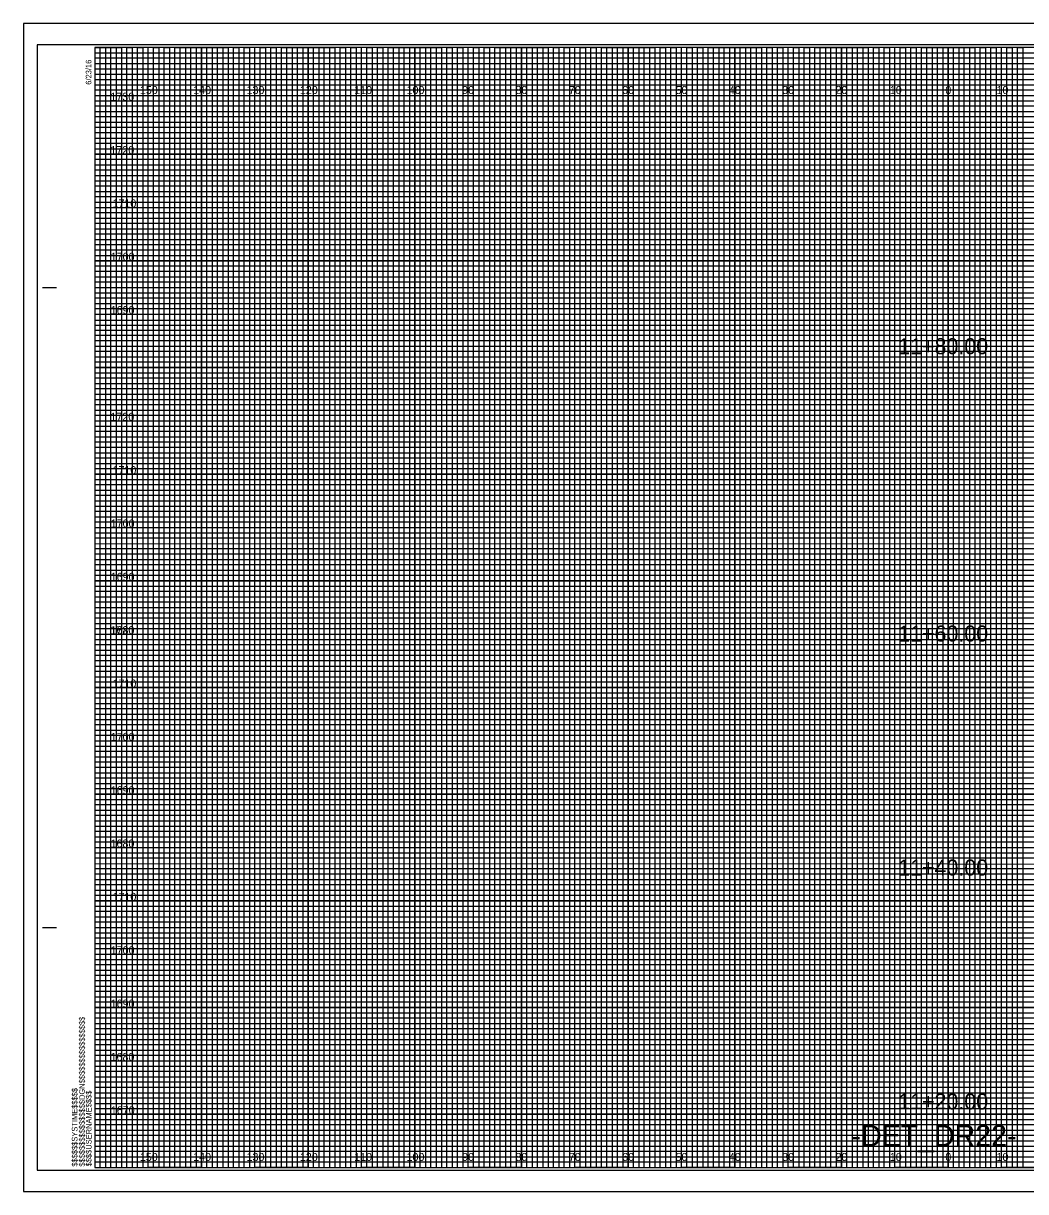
# Model space of a CAD drawing. Extents: x -13 to 323, y -5 to 1314.
# Drawn here: x -13.4 to 174.5, y 215.5 to 434.5 of the extents above; entities that cross this region are included whole.
import ezdxf

# ---------------------------------------------------------------- set-up
doc = ezdxf.new("R2010")
doc.units = 0
for name, color, linetype in [('Prop Horizontal Alignment', 7, 'Continuous'), ('Prop XS Alignment Label', 7, 'Continuous'), ('Raster_Level_0', 7, 'Continuous'), ('Scratch_Level_3', 7, 'Continuous'), ('Sheet Cross Section CELL', 7, 'Continuous'), ('Sheet Cross Section Grid Major CELL', 7, 'Continuous'), ('Sheet Cross Section Grid Middle CELL', 7, 'Continuous'), ('Sheet Cross Section Grid Minor 1 CELL', 7, 'Continuous'), ('Sheet Cross Section Grid Minor 2 CELL', 7, 'Continuous'), ('Sheet Cutting Line CELL', 7, 'Continuous'), ('Sheet DOT Grid CELL', 7, 'Continuous'), ('Sheet Plot Border Inside CELL', 7, 'Continuous'), ('Sheet Plot Border Outside CELL', 7, 'Continuous')]:
    doc.layers.add(name, color=color, linetype=linetype)

msp = doc.modelspace()

# ---------------------------------------------------------------- linework, layer by layer
at = {"layer": 'Sheet Cross Section CELL'}
for p, q in [((-9.8, 385), (-7.3, 385)), ((-9.7, 385), (-7.2, 385)), ((-9.8, 265), (-7.3, 265)), ((-9.7, 265), (-7.2, 265)), ((0, 220), (0, 220)), ((0, 220), (0, 220)), ((0, 220), (0, 220)), ((0, 220), (0, 220)), ((0, 220), (0, 220)), ((0, 220), (0, 220)), ((0, 220), (0, 220))]:
    msp.add_line(p, q, dxfattribs=at)
msp.add_lwpolyline([(320, 430), (0, 430), (0, 220), (320, 220)], close=True, dxfattribs=at)
at = {"layer": 'Sheet Cross Section Grid Major CELL'}
for p, q in [((10, 430), (0, 430)), ((10, 220), (10, 430)), ((30, 430), (20, 430)), ((20, 430), (20, 220)), ((30, 220), (30, 430)), ((50, 430), (40, 430)), ((40, 430), (40, 220)), ((50, 220), (50, 430)), ((70, 430), (60, 430)), ((60, 430), (60, 220)), ((70, 220), (70, 430)), ((90, 430), (80, 430)), ((80, 430), (80, 220)), ((90, 220), (90, 430)), ((110, 430), (100, 430)), ((100, 430), (100, 220)), ((110, 220), (110, 430)), ((130, 430), (120, 430)), ((120, 430), (120, 220)), ((130, 220), (130, 430)), ((150, 430), (140, 430)), ((140, 430), (140, 220)), ((150, 220), (150, 430)), ((170, 430), (160, 430)), ((160, 430), (160, 220)), ((170, 220), (170, 430)), ((20, 220), (10, 220)), ((40, 220), (30, 220)), ((60, 220), (50, 220)), ((80, 220), (70, 220)), ((100, 220), (90, 220)), ((120, 220), (110, 220)), ((140, 220), (130, 220)), ((160, 220), (150, 220)), ((180, 220), (170, 220))]:
    msp.add_line(p, q, dxfattribs=at)
for points in [[(0, 420), (320, 420), (320, 410), (0, 410)], [(0, 400), (320, 400), (320, 390), (0, 390)], [(0, 380), (320, 380), (320, 370), (0, 370)], [(0, 360), (320, 360), (320, 350), (0, 350)], [(0, 340), (320, 340), (320, 330), (0, 330)], [(0, 320), (320, 320), (320, 310), (0, 310)], [(0, 300), (320, 300), (320, 290), (0, 290)], [(0, 280), (320, 280), (320, 270), (0, 270)], [(0, 260), (320, 260), (320, 250), (0, 250)], [(0, 240), (320, 240), (320, 230), (0, 230)]]:
    msp.add_lwpolyline(points, dxfattribs=at)
at = {"layer": 'Sheet Cross Section Grid Middle CELL'}
for points in [[(0, 430), (5, 430), (5, 220), (15, 220), (15, 430), (25, 430), (25, 220), (35, 220), (35, 430), (45, 430), (45, 220), (55, 220), (55, 430), (65, 430), (65, 220), (75, 220), (75, 430), (85, 430), (85, 220), (95, 220), (95, 430), (105, 430), (105, 220), (115, 220), (115, 430), (125, 430), (125, 220), (135, 220), (135, 430), (145, 430), (145, 220), (155, 220), (155, 430), (165, 430), (165, 220), (175, 220)], [(0, 425), (275, 425)], [(0, 405), (320, 405), (320, 415), (0, 415)], [(0, 385), (320, 385), (320, 395), (0, 395)], [(0, 365), (320, 365), (320, 375), (0, 375)], [(0, 345), (320, 345), (320, 355), (0, 355)], [(0, 325), (320, 325), (320, 335), (0, 335)], [(0, 305), (320, 305), (320, 315), (0, 315)], [(0, 285), (320, 285), (320, 295), (0, 295)], [(0, 265), (320, 265), (320, 275), (0, 275)], [(0, 245), (320, 245), (320, 255), (0, 255)], [(0, 225), (320, 225), (320, 235), (0, 235)]]:
    msp.add_lwpolyline(points, dxfattribs=at)
at = {"layer": 'Sheet Cross Section Grid Minor 1 CELL'}
for p, q in [((0, 429), (260, 429)), ((260, 427.98), (0, 427.98)), ((0, 427.98), (0, 427)), ((0, 427), (260, 427)), ((260, 425.89), (0, 425.89)), ((0, 425.89), (0, 424)), ((0, 424), (320, 424))]:
    msp.add_line(p, q, dxfattribs=at)
for points in [[(0, 423), (270, 423), (320, 423), (320, 422), (0, 422)], [(0, 421), (320, 421), (320, 419), (0, 419)], [(0, 418), (320, 418), (320, 417), (0, 416.98)], [(0, 416), (320, 416), (320, 414), (0, 414)], [(0, 413), (320, 413), (320, 412), (0, 412)], [(0, 411), (320, 411), (320, 409), (0, 409)], [(0, 408), (320, 408), (320, 407), (0, 407)], [(0, 406), (320, 406), (320, 404), (0, 404)], [(0, 403), (320, 403), (320, 402), (0, 402)], [(0, 401), (320, 401), (320, 399), (0, 399)], [(0, 398), (320, 398), (320, 397), (0, 397)], [(0, 396), (320, 396), (320, 393.95), (320, 393), (320, 392), (0, 392)], [(0, 394), (320, 394), (320, 393), (0, 393)], [(0, 391), (320, 391), (320, 389), (0, 389.03)], [(0, 389.03), (320, 389), (320, 388), (0, 388)], [(0, 387), (320, 387), (320, 386), (0, 386)], [(0, 384), (320, 384), (320, 383), (0, 383)], [(0, 382), (320, 382), (320, 381), (0, 381)], [(-0.07, 378.89), (320, 378.89), (320, 377.88), (-0.07, 377.88)], [(0, 377), (320, 377), (320, 376), (0, 376)], [(0, 374), (320, 374), (320, 373), (0, 373)], [(0, 372), (320, 372), (320, 371), (0, 371)], [(0, 369), (320, 369), (320, 368), (0, 368)], [(0, 367), (320, 367), (320, 366), (0, 366)], [(0, 364), (320, 364), (320, 363), (0, 363)], [(0, 362), (320, 362), (320, 361), (0, 361)], [(0, 359), (320, 359), (319.99, 357.98), (0, 358)], [(0, 357), (320, 357), (320, 356), (0, 356)], [(0, 354), (320, 354), (320, 353), (0, 353)], [(0, 352), (320, 352), (320, 351), (0, 351)], [(0, 349), (320, 349), (320, 348), (0, 348)], [(0, 347), (320, 347), (320, 346), (0, 346)], [(0, 344), (320, 344), (320, 343), (0, 343)], [(0, 342), (320, 342), (320, 341), (0, 341)], [(0, 339), (320, 339), (320, 338), (0, 338)], [(0, 336.99), (320.07, 336.91), (320, 336), (0, 336)], [(0, 334), (320, 334), (320, 333), (0, 333)], [(0, 332), (320, 332), (320, 331), (0, 331)], [(0, 329), (320, 329), (320, 328), (0, 328)], [(0, 327), (320, 327), (320, 326), (0, 326)], [(0, 324), (320, 324), (320, 323), (0, 323)], [(0, 322), (320, 322), (320, 321), (0, 321)], [(0, 319), (320, 319), (320, 318), (0, 318)], [(0, 317), (320, 317), (320, 316), (0, 316)], [(0, 314), (320, 314), (320, 313), (0, 313)], [(0, 312), (320, 312), (320, 311), (0, 311)], [(0, 309), (320, 309), (320, 308), (0, 308)], [(0, 307), (320, 307), (320, 306), (0, 306)], [(0, 304), (320, 304), (320, 303), (0, 303)], [(0, 302), (320, 302), (320, 301), (0, 301)], [(0, 299), (320, 299), (319.99, 297.98), (0, 298)], [(0, 297), (320, 297), (320, 296), (0, 296)], [(0, 294), (320, 294), (320, 293), (0, 293)], [(0, 292), (320, 292), (320, 291), (0, 291)], [(0, 289), (320, 289), (320, 288), (0, 288)], [(0, 287), (320, 287), (320, 286), (0, 286)], [(0, 284), (320, 284), (320, 283), (0, 283)], [(0, 282), (320, 282), (320, 281), (0, 281)], [(0, 279), (320, 279), (320, 278), (0, 278)], [(0, 276.99), (320.07, 276.91), (320, 276), (0, 276)], [(0, 274), (320, 274), (320, 273), (0, 273)], [(0, 272), (320, 272), (320, 271), (0, 271)], [(0, 269), (320, 269), (320, 268), (0, 268)], [(0, 267), (320, 267), (320, 266), (0, 266)], [(0, 264), (320, 264), (320, 263), (0, 263)], [(0, 262), (320, 262), (320, 261), (0, 261)], [(0, 259), (320, 259), (320, 258), (0, 258)], [(0, 257), (320, 257), (320, 256), (0, 256)], [(0, 254), (320, 254), (320, 253), (0, 253)], [(0, 252), (320, 252), (320, 251), (0, 251)], [(0, 249), (320, 249), (320, 248), (0, 248)], [(0, 247), (320, 247), (320, 246), (0, 246)], [(0, 244), (320, 244), (320, 243), (0, 243)], [(0, 242), (320, 242), (320, 241), (0, 241)], [(0, 239), (320, 239), (320, 238), (0, 238)], [(0, 237), (320, 237), (320, 236), (0, 236)], [(0, 234), (320, 234), (320, 233), (0, 233)], [(0, 232), (320, 232), (320, 231), (0, 231)], [(0, 229), (320, 229), (320, 228), (0, 228)], [(0, 227), (320, 227), (320, 226), (0, 226)], [(0, 224), (320, 224), (320, 223), (0, 223)], [(0, 222), (320, 222), (320, 221), (0, 221)]]:
    msp.add_lwpolyline(points, dxfattribs=at)
at = {"layer": 'Sheet Cross Section Grid Minor 2 CELL'}
for points in [[(0, 220), (1, 220), (1, 430), (2, 430), (2, 220)], [(2, 220), (3, 220), (3, 430), (4, 430), (4, 220)], [(5, 220), (6, 220), (6, 430), (7, 430), (7, 220)], [(7, 220), (8, 220), (8, 430), (9, 430), (9, 220)], [(10, 220), (11, 220), (11, 430), (12, 430), (12, 220)], [(12, 220), (13, 220), (13, 430), (14, 430), (14, 220)], [(15, 220), (16, 220), (16, 430), (17, 430), (17, 220)], [(17, 220), (18, 220), (18, 430), (19, 430), (19, 220)], [(20, 220), (21, 220), (21, 430), (22, 430), (22, 220)], [(22, 220), (23, 220), (23, 430), (24, 430), (24, 220)], [(25, 220), (26, 220), (26, 430), (27, 430), (27, 220)], [(27, 220), (28, 220), (28, 430), (29, 430), (29, 220)], [(30, 220), (31, 220), (31, 430), (32, 430), (32, 220)], [(32, 220), (33, 220), (33, 430), (34, 430), (34, 220)], [(35, 220), (36, 220), (36, 430), (37, 430), (37, 220)], [(37, 220), (38, 220), (38, 430), (39, 430), (39, 220)], [(40, 220), (41, 220), (41, 430), (42, 430), (42, 220)], [(42, 220), (43, 220), (43, 430), (44, 430), (44, 220)], [(45, 220), (46, 220), (46, 430), (47, 430), (47, 220)], [(47, 220), (48, 220), (48, 430), (49, 430), (49, 220)], [(50, 220), (51, 220), (51, 430), (52, 430), (52, 220)], [(52, 220), (53, 220), (53, 430), (54, 430), (54, 220)], [(55, 220), (56, 220), (56, 430), (57, 430), (57, 220)], [(57, 220), (58, 220), (58, 430), (59, 430), (59, 220)], [(60, 220), (61, 220), (61, 430), (62, 430), (62, 220)], [(62, 220), (63, 220), (63, 430), (64, 430), (64, 220)], [(65, 220), (66, 220), (66, 430), (67, 430), (67, 220)], [(67, 220), (68, 220), (68, 430), (69, 430), (69, 220)], [(70, 220), (71, 220), (71, 430), (72, 430), (72, 220)], [(72, 220), (73, 220), (73, 430), (74, 430), (74, 220)], [(75, 220), (76, 220), (76, 430), (77, 430), (77, 220)], [(77, 220), (78, 220), (78, 430), (79, 430), (79, 220)], [(80, 220), (81, 220), (81, 430), (82, 430), (82, 220)], [(82, 220), (83, 220), (83, 430), (84, 430), (84, 220)], [(85, 220), (86, 220), (86, 430), (87, 430), (87, 220)], [(87, 220), (88, 220), (88, 430), (89, 430), (89, 220)], [(90, 220), (91, 220), (91, 430), (92, 430), (92, 220)], [(92, 220), (93, 220), (93, 430), (94, 430), (94, 220)], [(95, 220), (96, 220), (96, 430), (97, 430), (97, 220)], [(97, 220), (98, 220), (98, 430), (99, 430), (99, 220)], [(100, 220), (101, 220), (101, 430), (102, 430), (102, 220)], [(102, 220), (103, 220), (103, 430), (104, 430), (104, 220)], [(105, 220), (106, 220), (106, 430), (107, 430), (107, 220)], [(107, 220), (108, 220), (108, 430), (109, 430), (109, 220)], [(110, 220), (111, 220), (111, 430), (112, 430), (112, 220)], [(112, 220), (113, 220), (113, 430), (114, 430), (114, 220)], [(115, 220), (116, 220), (116, 430), (117, 430), (117, 220)], [(117, 220), (118, 220), (118, 430), (119, 430), (119, 220)], [(120, 220), (121, 220), (121, 430), (122, 430), (122, 220)], [(122, 220), (123, 220), (123, 430), (124, 430), (124, 220)], [(125, 220), (126, 220), (126, 430), (127, 430), (127, 220)], [(127, 220), (128, 220), (128, 430), (129, 430), (129, 220)], [(130, 220), (131, 220), (131, 430), (132, 430), (132, 220)], [(132, 220), (133, 220), (133, 430), (134, 430), (134, 220)], [(135, 220), (136, 220), (136, 430), (137, 430), (137, 220)], [(137, 220), (138, 220), (138, 430), (139, 430), (139, 220)], [(140, 220), (141, 220), (141, 430), (142, 430), (142, 220)], [(142, 220), (143, 220), (143, 430), (144, 430), (144, 220)], [(145, 220), (146, 220), (146, 430), (147, 430), (147, 220)], [(147, 220), (148, 220), (148, 430), (149, 430), (149, 220)], [(150, 220), (151, 220), (151, 430), (152, 430), (152, 220)], [(152, 220), (153, 220), (153, 430), (154, 430), (154, 220)], [(155, 220), (156, 220), (156, 430), (157, 430), (157, 220)], [(157, 220), (158, 220), (158, 430), (159, 430), (159, 220)], [(160, 220), (161, 220), (161, 430), (162, 430), (162, 220)], [(162, 220), (163, 220), (163, 430), (164, 430), (164, 220)], [(165, 220), (166, 220), (166, 430), (167, 430), (167, 220)], [(167, 220), (168, 220), (168, 430), (169, 430), (169, 220)], [(170, 220), (171, 220), (171, 430), (172, 430), (172, 220)], [(172, 220), (173, 220), (173, 430), (174, 430), (174, 220)]]:
    msp.add_lwpolyline(points, dxfattribs=at)
at = {"layer": 'Sheet Cutting Line CELL'}
for p, q in [((323.3, 434.5), (-13.4, 434.5)), ((-13.4, 434.5), (-13.4, 215.5)), ((-13.4, 215.5), (323.3, 215.5))]:
    msp.add_line(p, q, dxfattribs=at)
at = {"layer": 'Sheet DOT Grid CELL'}
for p, q in [((10, 220), (10, 430)), ((20, 220), (20, 430)), ((30, 220), (30, 430)), ((40, 220), (40, 430)), ((50, 220), (50, 430)), ((60, 220), (60, 430)), ((70, 220), (70, 430)), ((80, 220), (80, 430)), ((90, 220), (90, 430)), ((100, 220), (100, 430)), ((110, 220), (110, 430)), ((120, 220), (120, 430)), ((130, 220), (130, 430)), ((140, 220), (140, 430)), ((150, 220), (150, 430)), ((160, 220), (160, 430)), ((170, 220), (170, 430)), ((0, 420), (320, 420)), ((0, 410), (320, 410)), ((0, 400), (320, 400)), ((0, 390), (320, 390)), ((0, 380), (320, 380)), ((0, 370), (320, 370)), ((0, 360), (320, 360)), ((0, 350), (320, 350)), ((0, 340), (320, 340)), ((0, 330), (320, 330)), ((0, 320), (320, 320)), ((0, 310), (320, 310)), ((0, 300), (320, 300)), ((0, 290), (320, 290)), ((0, 280), (320, 280)), ((0, 270), (320, 270)), ((0, 260), (320, 260)), ((0, 250), (320, 250)), ((0, 240), (320, 240)), ((0, 230), (320, 230))]:
    msp.add_line(p, q, dxfattribs=at)
at = {"layer": 'Sheet Plot Border Inside CELL'}
msp.add_lwpolyline([(-10.8, 219.5), (322.4, 219.5), (322.4, 430.5), (-10.8, 430.5)], close=True, dxfattribs=at)
at = {"layer": 'Sheet Plot Border Outside CELL'}
msp.add_lwpolyline([(-13.4, 215.5), (323.3, 215.5), (323.3, 434.5), (-13.4, 434.5)], close=True, dxfattribs=at)

# ---------------------------------------------------------------- texts
at = {"layer": 'Prop Horizontal Alignment'}
for s, p in [('11+80.00', (150.62, 372.48)), ('11+60.00', (150.62, 318.62)), ('11+40.00', (150.62, 274.76)), ('11+20.00', (150.62, 230.9))]:
    msp.add_text(s, height=3, dxfattribs=at).set_placement(p)
at = {"layer": 'Prop XS Alignment Label'}
msp.add_text('-DET_DR22-', height=4, dxfattribs=at).set_placement((141.87, 224))
at = {"layer": 'Raster_Level_0'}
for s, p in [('150', (8.44, 421.25)), ('140', (18.44, 421.25)), ('130', (28.44, 421.25)), ('120', (38.44, 421.25)), ('110', (48.62, 421.25)), ('100', (58.44, 421.25)), ('90', (68.86, 421.25)), ('80', (78.86, 421.25)), ('70', (88.86, 421.25)), ('60', (98.86, 421.25)), ('50', (108.86, 421.25)), ('40', (118.86, 421.25)), ('30', (128.86, 421.25)), ('20', (138.86, 421.25)), ('10', (149.04, 421.25)), ('0', (159.45, 421.25)), ('0', (159.45, 421.25)), ('10', (169.04, 421.25)), ('150', (8.44, 221.25)), ('140', (18.44, 221.25)), ('130', (28.44, 221.25)), ('120', (38.44, 221.25)), ('110', (48.62, 221.25)), ('100', (58.44, 221.25)), ('90', (68.86, 221.25)), ('80', (78.86, 221.25)), ('70', (88.86, 221.25)), ('60', (98.86, 221.25)), ('50', (108.86, 221.25)), ('40', (118.86, 221.25)), ('30', (128.86, 221.25)), ('20', (138.86, 221.25)), ('10', (149.04, 221.25)), ('0', (159.45, 221.25)), ('0', (159.45, 221.25)), ('10', (169.04, 221.25))]:
    msp.add_text(s, height=1.5, dxfattribs=at).set_placement(p)
at = {"layer": 'Scratch_Level_3'}
for s, p in [('1730', (2.92, 420)), ('1720', (2.93, 410)), ('1710', (3.31, 400)), ('1700', (2.98, 390)), ('1690', (2.97, 380)), ('1720', (2.93, 360)), ('1710', (3.31, 350)), ('1700', (2.98, 340)), ('1690', (2.97, 330)), ('1720', (2.93, 320)), ('1680', (2.95, 320)), ('1710', (3.31, 310)), ('1700', (2.98, 300)), ('1690', (2.97, 290)), ('1680', (2.95, 280)), ('1710', (3.31, 270)), ('1700', (2.98, 260)), ('1690', (2.97, 250)), ('1680', (2.95, 240)), ('1670', (3, 230))]:
    msp.add_text(s, height=1.5, dxfattribs=at).set_placement(p)
at = {"layer": 'Sheet Cross Section CELL'}
for s, p in [('6/23/16', (-0.65, 423)), ('$$$$$$$$$$$$$$$$DGN$$$$$$$$$$$$$$$$', (-1.88, 220.18)), ('$$$$$$SYSTIME$$$$$', (-3.26, 220.18)), ('$$$$USERNAME$$$$', (-0.62, 220.23))]:
    msp.add_text(s, height=1.05, rotation=90, dxfattribs=at).set_placement(p)

doc.saveas('drawing.dxf')
